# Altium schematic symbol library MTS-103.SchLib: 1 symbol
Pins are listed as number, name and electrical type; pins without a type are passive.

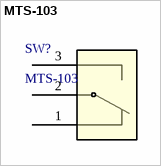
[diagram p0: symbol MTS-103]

## MTS-103
designator SW?
Description; Manufacturer_Name: Jameco Valuepro
footprint MTS-103_JCV
pins: 1, 2, 3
